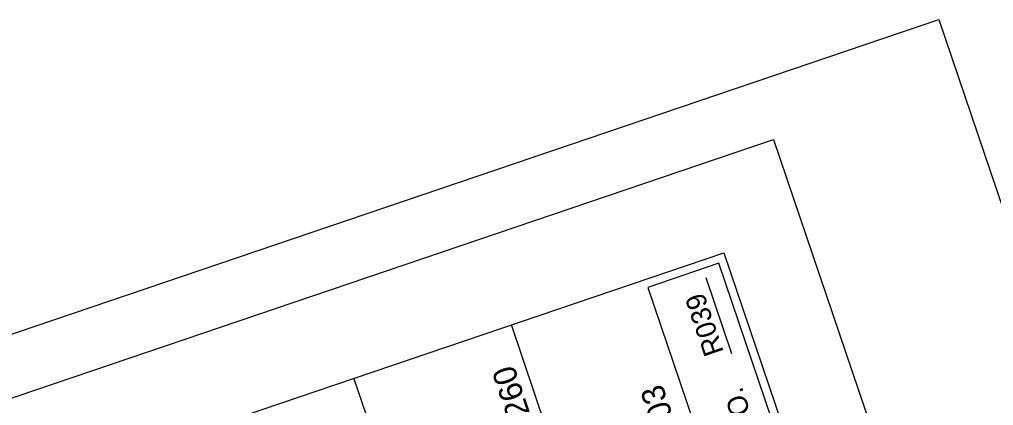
# Model space of a CAD drawing. Extents: x 2150318 to 2152065, y 143281 to 145371.
# Drawn here: x 2151178.4 to 2151471.2, y 145254.7 to 145370.7 of the extents above; entities that cross this region are included whole.
import ezdxf

# ---------------------------------------------------------------- set-up
doc = ezdxf.new("R2010")
doc.units = 0
for name, color, linetype in [('SHT_Plan_Profile_Sheet_Elev_Txt', 7, 'Continuous'), ('SHT_Plan_Profile_Sheet_Sta_Txt', 7, 'Continuous'), ('SHT_Plan_Profile_Sheet_Txt', 7, 'Continuous'), ('SHT_Plot_Shape_Full', 7, 'Continuous'), ('SHT_Plot_Shape_Half', 7, 'Continuous'), ('SHT_Profile_Grid_Major', 7, 'Continuous'), ('SHT_Sheet_Border', 7, 'Continuous'), ('SHT_Standard_Sheet_Lines', 7, 'Continuous')]:
    doc.layers.add(name, color=color, linetype=linetype)

msp = doc.modelspace()

# ---------------------------------------------------------------- linework, layer by layer
at = {"layer": 'SHT_Plot_Shape_Full'}
msp.add_lwpolyline([(2150896.74, 143280.62), (2150318.46, 144985.2), (2151454.85, 145370.71), (2152033.12, 143666.13)], close=True, dxfattribs=at)
at = {"layer": 'SHT_Plot_Shape_Half'}
msp.add_lwpolyline([(2150909.49, 143371.4), (2150363.35, 144981.29), (2151405.04, 145334.68), (2151951.18, 143724.79)], close=True, dxfattribs=at)
at = {"layer": 'SHT_Profile_Grid_Major'}
for p, q in [((2151832.26, 143787.41), (2151326.27, 145278.92)), ((2151784.91, 143771.34), (2151278.93, 145262.85))]:
    msp.add_line(p, q, dxfattribs=at)
at = {"layer": 'SHT_Sheet_Border'}
for points in [[(2150901.85, 143471.77), (2150395.86, 144963.28), (2151390.2, 145300.6), (2151896.19, 143809.09)], [(2151445.23, 145060.56), (2151466.54, 145067.79), (2151388.63, 145297.43), (2151367.32, 145290.2)]]:
    msp.add_lwpolyline(points, close=True, dxfattribs=at)
at = {"layer": 'SHT_Standard_Sheet_Lines'}
msp.add_line((2151392.59, 145270.2), (2151384.84, 145293.04), dxfattribs=at)

# ---------------------------------------------------------------- texts
at = {"layer": 'SHT_Plan_Profile_Sheet_Elev_Txt'}
msp.add_text('1260', height=7, rotation=108.7393, dxfattribs=at).set_placement((2151333.6, 145247.5))
at = {"layer": 'SHT_Plan_Profile_Sheet_Sta_Txt'}
msp.add_text('103', height=7, rotation=108.7393, dxfattribs=at).set_placement((2151376.55, 145246.68))
at = {"layer": 'SHT_Plan_Profile_Sheet_Txt'}
for s, p in [('R039', (2151390.2, 145270.79)), ('SHEET NO.', (2151409.4, 145219.69))]:
    msp.add_text(s, height=6, rotation=108.7393, dxfattribs=at).set_placement(p)

doc.saveas('drawing.dxf')
